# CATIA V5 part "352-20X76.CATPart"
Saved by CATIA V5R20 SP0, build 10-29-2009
Part number: 352-20X76
Definition: NONE
Nomenclature: 352-20X76
Source: Unknown
Description: 352-20X76
Bounding box of the stored display mesh (mm): x 0 to 76, y -14 to 14, z -14 to 14
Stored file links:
  C:\Users\Utente\Desktop\IO LAVORO\3D X SITO CF\X SITO\PLASTICA\352\352-20X76.CATPart
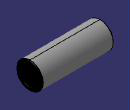
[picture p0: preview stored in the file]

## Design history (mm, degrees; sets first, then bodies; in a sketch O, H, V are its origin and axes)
Body1 "352-20X76" (main body)
  Solid1: solid without history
